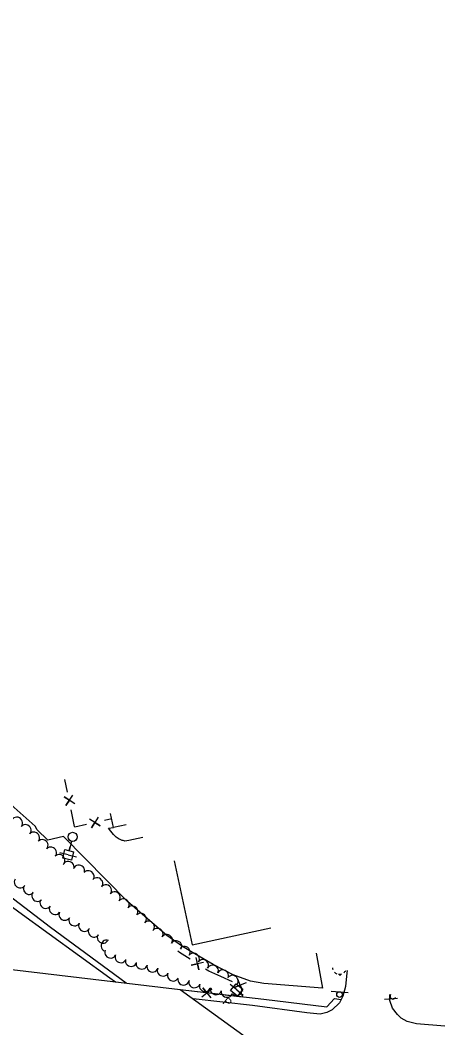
# Model space of a CAD drawing. Extents: x 1746010 to 1754829, y 655801 to 663091.
# Drawn here: x 1750426 to 1750802, y 660007 to 660899 of the extents above; entities that cross this region are included whole.
import ezdxf

# ---------------------------------------------------------------- set-up
doc = ezdxf.new("R2010")
doc.units = 0
for name, color, linetype in [('SURVEY - AERIAL SURVEY - Photo Control - Points - Elevations', 7, 'Continuous'), ('SURVEY - AERIAL SURVEY - Photo Control - Points - Locators', 7, 'Continuous'), ('SURVEY - AERIAL SURVEY - Photo Control with Text', 7, 'Continuous'), ('SURVEY - CENTERLINE - Existing Roads - Development', 7, 'Continuous'), ('SURVEY - CENTERLINE - Existing Roads Curve Text', 7, 'Continuous'), ('SURVEY - CENTERLINE - Existing Roads Text', 7, 'Continuous')]:
    doc.layers.add(name, color=color, linetype=linetype)

msp = doc.modelspace()

# ---------------------------------------------------------------- linework, layer by layer
at = {"layer": 'SURVEY - AERIAL SURVEY - Photo Control - Points - Elevations'}
msp.add_lwpolyline([(1750204.41, 660084.58), (1750567.39, 660041.45), (1750676.22, 659962.69), (1750316.04, 660004.98)], dxfattribs=at)
at = {"layer": 'SURVEY - AERIAL SURVEY - Photo Control - Points - Locators'}
for points in [[(1749387.11, 660899.35), (1749486.53, 660821.3), (1749560.37, 660763.13), (1749636.02, 660704.45), (1749732.4, 660629.58), (1749833.07, 660551.99), (1749920.33, 660484.88), (1750008.5, 660418.55), (1750084.45, 660361.56), (1750166.82, 660299.99), (1750252.84, 660236.3), (1750339.47, 660172.61), (1750424.46, 660110.17), (1750505.09, 660051.79), (1750510.03, 660048.27)], [(1750438.83, 660185.91), (1750420.38, 660202.58), (1750402.21, 660219.96), (1750386.13, 660237.65), (1750374.12, 660251.65)], [(1750464.12, 660176.75), (1750450.14, 660173.71), (1750440.82, 660182.66), (1750438.83, 660185.91)], [(1750503.81, 660184.27), (1750508.32, 660184.78)], [(1750569.27, 660079.53), (1750555.4, 660089.22), (1750520.64, 660119.21), (1750464.12, 660176.75)], [(1750534.21, 660176), (1750521.78, 660173.3), (1750518.44, 660172.71)], [(1750519.47, 660047.15), (1750452.55, 660096.14), (1750387.84, 660145.49), (1750369.91, 660159), (1750365.71, 660168.08)], [(1750687.77, 660073.49), (1750693.2, 660042.72), (1750641.28, 660046.79), (1750629.64, 660048.92), (1750614.33, 660054.39), (1750596.62, 660063.4), (1750578.36, 660074.3), (1750569.27, 660079.53)], [(1750715.01, 660058.3), (1750714.91, 660056.04), (1750713.7, 660044.13), (1750711.46, 660035.57), (1750708.34, 660029.5), (1750701.89, 660023.51), (1750697.24, 660021.14), (1750691.32, 660019.65), (1750679.41, 660020.86), (1750631.28, 660027.14), (1750578.75, 660033.23)], [(1750567.39, 660041.45), (1750641.3, 660032.89)], [(1750641.28, 660032.89), (1750697.26, 660026), (1750703.91, 660033.35), (1750709.91, 660032.56)], [(1750801.65, 660008.85), (1750776.49, 660011.08), (1750768.18, 660013.15), (1750763.04, 660015.99), (1750759.61, 660019.14), (1750755.3, 660024.78), (1750752.99, 660031.65), (1750753.06, 660037.09)]]:
    msp.add_lwpolyline(points, dxfattribs=at)
msp.add_spline([(1750518.44, 660172.71), (1750515.23, 660173.66), (1750511.44, 660175.55), (1750508.28, 660178.69), (1750503.77, 660184.32)], degree=3, dxfattribs=at)
at = {"layer": 'SURVEY - AERIAL SURVEY - Photo Control with Text'}
for p, q in [((1750701.02, 660039.92), (1750715.99, 660038.88)), ((1750759.86, 660033.3), (1750748.3, 660032.55))]:
    msp.add_line(p, q, dxfattribs=at)
msp.add_circle((1750708.38, 660036.95), 2.5, dxfattribs=at)
msp.add_arc((1750755.58, 660035.48), 2.5, 146.76871, 334.95683, dxfattribs=at)
at = {"layer": 'SURVEY - CENTERLINE - Existing Roads - Development'}
for points in [[(1750467.58, 660216.13), (1750465.3, 660227.18)], [(1750473.9, 660205.8), (1750464.47, 660211.92), (1750469.18, 660208.91), (1750466.07, 660204.18), (1750472.3, 660213.54)], [(1750473.87, 660185.68), (1750470.84, 660200.37)], [(1750494.71, 660193.98), (1750488.78, 660184.43), (1750491.7, 660189.2), (1750496.48, 660186.19), (1750487.01, 660192.23)], [(1750506.68, 660192.5), (1750500.2, 660191.03)], [(1750519.38, 660187.02), (1750508.34, 660184.67), (1750505.69, 660197.18)], [(1750484.51, 660187.46), (1750474, 660185.07), (1750473.87, 660185.68)], [(1750561.93, 660155.42), (1750577.83, 660081.04), (1750647.49, 660095.94)], [(1750566.72, 660074.27), (1750565.17, 660075.27)], [(1750576.28, 660068.11), (1750566.72, 660074.27)], [(1750588.07, 660065.35), (1750577.08, 660062.98), (1750582.54, 660064.19), (1750583.71, 660058.71), (1750581.45, 660069.63)], [(1750603.21, 660052.84), (1750592.57, 660057.6), (1750589.77, 660059.41)], [(1750613.61, 660048.18), (1750603.21, 660052.84)], [(1750625.69, 660047.24), (1750615.21, 660043.22), (1750620.41, 660045.25), (1750622.42, 660040), (1750618.48, 660050.46)], [(1750567.39, 660041.45), (1750582.28, 660039.67)], [(1750586.47, 660035.06), (1750595.24, 660042.01), (1750590.91, 660038.53), (1750587.4, 660042.95), (1750594.32, 660034.12)], [(1750598.27, 660037.75), (1750609.58, 660036.39)], [(1750609.58, 660036.39), (1750622.42, 660034.84), (1750622.1, 660036.89)]]:
    msp.add_lwpolyline(points, dxfattribs=at)
at = {"layer": 'SURVEY - CENTERLINE - Existing Roads Curve Text'}
for p, q in [((1750471.14, 660172.73), (1750469.06, 660164.28)), ((1750469.16, 660164.67), (1750469.92, 660167.78)), ((1750468.13, 660160.49), (1750460.85, 660162.28)), ((1750468.13, 660160.49), (1750475.42, 660158.71)), ((1750709.03, 660053.59), (1750708.91, 660054.98)), ((1750617.35, 660041.01), (1750611.49, 660045.69)), ((1750617.35, 660041.01), (1750623.22, 660036.33))]:
    msp.add_line(p, q, dxfattribs=at)
for points in [[(1750463.42, 660157.63), (1750465.27, 660165.21), (1750472.85, 660163.35), (1750470.99, 660155.78)], [(1750616.74, 660046.49), (1750622.83, 660041.63), (1750617.97, 660035.53), (1750611.87, 660040.4)]]:
    msp.add_lwpolyline(points, close=True, dxfattribs=at)
msp.add_circle((1750472.06, 660176.52), 4, dxfattribs=at)
for start, end in [(184.82682, 199.44769), (308.38956, 333.1596), (226.70469, 247.0472), (262.34775, 288.86306)]:
    msp.add_arc((1750708.34, 660061.16), 6.25, start, end, dxfattribs=at)
at = {"layer": 'SURVEY - CENTERLINE - Existing Roads Text'}
for centre, major_axis in [((1750422.94, 660189.11), (3.75, -3.3)), ((1750430.45, 660182.5), (3.75, -3.3)), ((1750437.95, 660175.89), (3.75, -3.3)), ((1750445.46, 660169.29), (3.75, -3.3)), ((1750452.97, 660162.68), (3.75, -3.3)), ((1750460.47, 660156.07), (3.75, -3.3)), ((1750468.34, 660150.09), (4.72, -1.65)), ((1750477.76, 660146.81), (4.72, -1.65)), ((1750486.18, 660141.77), (3.9, -3.13)), ((1750425.35, 660136.09), (-4.11, 2.85)), ((1750493.92, 660135.54), (3.9, -3.13)), ((1750433.46, 660130.34), (-3.8, 3.25)), ((1750501.66, 660129.31), (3.9, -3.13)), ((1750509.43, 660123.07), (3.9, -3.13)), ((1750440.7, 660124.16), (-3.8, 3.25)), ((1750447.98, 660118.02), (-4.19, 2.73)), ((1750517.22, 660116.81), (3.9, -3.13)), ((1750456.35, 660112.56), (-4.19, 2.73)), ((1750525.02, 660110.55), (3.9, -3.13)), ((1750464.9, 660107.41), (-4.35, 2.46)), ((1750473.59, 660102.49), (-4.35, 2.46)), ((1750532.5, 660103.97), (3.59, -3.49)), ((1750539.63, 660097.04), (3.59, -3.49)), ((1750482.28, 660097.58), (-4.35, 2.46)), ((1750490.78, 660092.53), (-4.16, 2.77)), ((1750547.28, 660090.74), (4.18, -2.75)), ((1750498.84, 660087.16), (-4.16, 2.77)), ((1750501.92, 660080.25), (1.84, 4.65)), ((1750555.58, 660085.26), (4.18, -2.75)), ((1750563.89, 660079.79), (4.18, -2.75)), ((1750505.57, 660074.02), (-4.54, 2.1)), ((1750571.25, 660074.71), (4.07, -2.91)), ((1750514.57, 660069.85), (-4.54, 2.1)), ((1750523.8, 660066.58), (-4.85, 1.23)), ((1750579.38, 660068.89), (4.07, -2.91)), ((1750587.51, 660063.07), (4.07, -2.91)), ((1750533.25, 660064.18), (-4.85, 1.23)), ((1750542.75, 660061.58), (-4.81, 1.36)), ((1750551.95, 660058.02), (-4.47, 2.24)), ((1750596.19, 660058.19), (4.52, -2.14)), ((1750605.22, 660053.92), (4.52, -2.14)), ((1750560.91, 660053.64), (-4.52, 2.13)), ((1750570.18, 660050.08), (-4.87, 1.12)), ((1750579.87, 660047.72), (-4.71, 1.69)), ((1750613.84, 660049.11), (3.63, -3.44)), ((1750589.28, 660044.35), (-4.71, 1.69)), ((1750598.86, 660041.51), (-4.82, 1.31)), ((1750608.59, 660039.22), (-4.91, 0.93)), ((1750617.39, 660040.8), (-3.61, -3.46))]:
    msp.add_ellipse(centre, major_axis=major_axis, ratio=0.940188, start_param=0, end_param=3.141593, dxfattribs=at)

# ---------------------------------------------------------------- texts
at = {"layer": 'SURVEY - CENTERLINE - Existing Roads Curve Text'}
msp.add_text('P', height=7.48, rotation=321.39, dxfattribs=at).set_placement((1750604.14, 660029.43))

doc.saveas('drawing.dxf')
